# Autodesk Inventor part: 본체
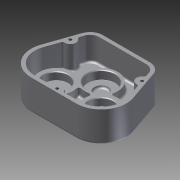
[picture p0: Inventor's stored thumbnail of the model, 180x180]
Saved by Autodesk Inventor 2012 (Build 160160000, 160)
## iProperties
Created: 2014-12
Part Number: 본체
Material: Default
Document SubType Name: Modeling
Designer: Owner
Density: 1 g/cm^3
Mass: 243.559 g
Surface Area: 720.583 cm^2
Volume: 243.559 cm^3
Author: Owner
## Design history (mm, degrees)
sketch "스케치1"
  geometry: L1 (-34.162, 68.527)-(34.162, 68.527); L2 (51.181, 56.389)-(66.565, 11.723); L3 (32.527, -36)-(-32.527, -36); L4 (-66.565, 11.723)-(-51.181, 56.389); L5 (34.162, 63.527)-(-34.162, 63.527); L6 (-46.453, 54.76)-(-61.837, 10.095); L7 (-32.527, -31)-(32.527, -31); L8 (61.837, 10.095)-(46.453, 54.76); C1 r 18 at (0, 32.527); C2 r 7.75 at (-32.527, 0); C3 r 7.75 at (32.527, 0); A1 r 18 centre (-34.162, 50.527) between (-34.162, 68.527) and (-51.181, 56.389); A2 r 18 centre (34.162, 50.527) between (51.181, 56.389) and (34.162, 68.527); A3 r 36 centre (32.527, 0) between (32.527, -36) and (66.565, 11.723); A4 r 36 centre (-32.527, 0) between (-66.565, 11.723) and (-32.527, -36); A5 r 13 centre (-34.162, 50.527) between (-34.162, 63.527) and (-46.453, 54.76); A6 r 31 centre (-32.527, 0) between (-61.837, 10.095) and (-32.527, -31); A7 r 31 centre (32.527, 0) between (32.527, -31) and (61.837, 10.095); A8 r 13 centre (34.162, 50.527) between (46.453, 54.76) and (34.162, 63.527); 4 further points
  constraints: 16 end point, 16 point on circle, 11 centre point, 5 tangent, 4 point on line, 2 coincident, 2 equal radius, 2 horizontal alignment, 2 parallel, 2 vertical alignment, 1 equal length, 1 horizontal, 1 midpoint, 7 other
  dimensions: "d0" = 94 distance of point (-47, 68.527) point (47, 68.527); "d1" = 36 diameter of C1; "d2" = 15.5 diameter of C2; "d3" = 36 distance from line of C3.centre L3; "d4" = 36 distance from line of C1.centre L1; "d5" = 46 distance of C2.centre C1.centre; "d6" = 46 distance of C3.centre C1.centre; "d7" = 90 deg dimension on C1.centre C2.centre C3.centre; "d10" = 18 radius of A1; "d11" = 36 radius of A3; "d12" = 36 radius of A4; "d13" = 5 distance between parallel lines of L2 L8
extrude "돌출1" new body sketch "스케치1" distance "d14" = 44; taper "d15" = 0 deg
extrude "돌출2" cut sketch "스케치1" distance "d16" = 34; taper "d17" = 0 deg
sketch "스케치2"
  geometry: L1 (46.453, 54.76)-(61.837, 10.095) reference; L2 (51.181, 56.389)-(66.565, 11.723) reference; L3 (-34.162, 68.527)-(34.162, 68.527) reference; A1 r 8 centre (51.7, 39.527) between (54.394, 47.06) and (58.461, 35.251); 1 further point
  constraints: 3 point on line, 2 point on circle, 1 centre point
  dimensions: "d18" = 16 diameter of A1; "d19" = 29 distance from line of A1.centre L3
extrude "돌출3" join sketch "스케치2" stored distance "d20" = 41; taper "d21" = 0 deg
hole "구멍1" diameter "d24" = 4.134; stored, may be unused: countersink angle "d28" = 90 deg, drill point angle "d30" = 118 deg; dims "d25" = 20, "d26" = 4, "d27" = 2, "d29" = 23, "d31" = 10, "d32" = 10
sketch "스케치3"
  geometry: L1 (32.527, -31)-(-32.527, -31) reference; L2 (32.527, -36)-(-32.527, -36) reference; A1 r 8 centre (0, -31) between (6.245, -36) and (-6.245, -36); 1 further point
  constraints: 2 point on circle, 2 point on line, 1 centre point, 1 midpoint
  dimensions: "d33" = 16 diameter of A1
extrude "돌출4" join sketch "스케치3" stored distance "d34" = 0; taper "d35" = 0 deg
hole "구멍2" diameter "d38" = 4.134; stored, may be unused: countersink angle "d42" = 90 deg, drill point angle "d44" = 118 deg; dims "d36" = 10, "d37" = 10, "d39" = 20, "d40" = 4, "d41" = 2, "d43" = 23
node "작업 평면1"
sketch "스케치4"
  geometry: L1 (7.75, -44)-(-7.75, -44) reference; L2 (7.75, -34)-(-7.75, -34) reference; L3 (0, -23)-(0, -51); L4 (-24, -23)-(-24, -34); L5 (-20, -44)-(-18.766, -51); L6 (-18.766, -51)-(-15, -51); L7 (-15, -51)-(-15, -44); L8 (-20, -44)-(-7.75, -44); L9 (-24, -23)-(-17.5, -23); L10 (-17.5, -23)-(-17.5, -34); L11 (-24, -34)-(-7.75, -34); L12 (11.723, -44)-(-36, -44) reference; 2 further points
  constraints: 18 end point, 4 parallel, 3 perpendicular, 2 horizontal alignment, 2 point on line, 1 collinear, 1 midpoint, 1 vertical alignment
  dimensions: "d45" = 7 distance from line of L3.end L1; "d46" = 11 distance from line of L3.start L2; "d47" = 48 diameter of L4 L3; "d48" = 35 diameter of L10 L3; "d49" = 100 deg angle of L12 L5; "d50" = 40 diameter of L5.start L3; "d51" = 30 diameter of L7 L3
revolve "회전1" sketch "스케치4" stored, may be unused: angle "d52" = 90 deg
sketch "스케치5"
  geometry: L1 (20, -44)-(-20, -44) reference; L2 (-24, -34)-(24, -34) reference; L3 (-24, -23)-(24, -23) reference; L4 (32.527, -23)-(32.527, -34); L5 (68.527, 0)-(68.527, -44) reference; L6 (56.527, -23)-(56.527, -34); L7 (56.527, -23)-(52.527, -23); L8 (52.527, -23)-(52.527, -34); L9 (52.527, -34)-(56.527, -34); 1 further point
  constraints: 10 end point, 3 horizontal alignment, 3 perpendicular, 2 parallel
  dimensions: "d53" = 36 distance from line of L4.end L5; "d54" = 48 diameter of L6 L4; "d55" = 40 diameter of L8 L4; "d56" = 11 distance of L4.start L4.end
revolve "회전2" sketch "스케치5" stored, may be unused: angle "d57" = 90 deg
fillet "모깎기1" dims "d58" = 3
fillet "모깎기2" dims "d59" = 3
fillet "모깎기3" dims "d60" = 3
hole "구멍4" diameter "d83" = 40; stored, may be unused: countersink angle "d87" = 90 deg, drill point angle "d89" = 0 deg; dims "d79" = 10, "d80" = 10, "d84" = 20, "d85" = 4, "d86" = 2, "d88" = 1
hole "구멍3" diameter "d63" = 20; stored, may be unused: countersink angle "d67" = 90 deg, drill point angle "d69" = 0 deg; dims "d64" = 20, "d65" = 4, "d66" = 2, "d68" = 3, "d90" = 10, "d91" = 10
fillet "모깎기4" dims "d70" = 3
fillet "모깎기5" dims "d71" = 0.3, "d72" = 0.1
chamfer "모따기1" distance "d73" = 1; stored, may be unused: second distance "d74" = 2, angle "d75" = 45 deg
sketch "스케치6"
  geometry: L1 (34.162, 68.527)-(-34.162, 68.527) reference; 2 further points
  constraints: 1 vertical alignment, 1 other
  dimensions: "d76" = 30 distance from line of point (0, 38.527) L1
feature "엠보싱1" sketch "스케치6" dims "d0" = 94, "d1" = 36, "d2" = 15.5, "d3" = 36, "d4" = 36, "d5" = 46, "d6" = 46, "d7" = 90 deg, "d10" = 18, "d11" = 36, "d12" = 36, "d13" = 5, "d77" = 1, "d78" = 0
node "솔리드1"
mirror "대칭1"
mirror "대칭2"
other parameters: "d8" = 72, "d9" = 72
